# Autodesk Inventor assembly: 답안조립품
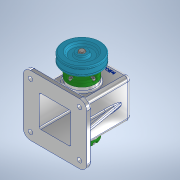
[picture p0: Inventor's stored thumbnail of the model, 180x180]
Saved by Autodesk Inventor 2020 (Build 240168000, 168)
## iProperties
Created: 2022-11
Part Number: 답안조립품
Document SubType Name: Assembly
Designer: USER
Author: USER
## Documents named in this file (16)
- C:\Users\USER\Desktop\721106V1004\답안조립품.iam
- C:\Users\USER\Desktop\721106V1004\본체1.ipt
- C:\Users\USER\Desktop\721106V1004\핀 5 x 18.ipt
- C:\Users\USER\Desktop\721106V1004\V벨트풀리.ipt
- C:\Users\USER\Desktop\721106V1004\고정핀 1.2 x 10.ipt
- C:\Users\USER\Desktop\721106V1004\뒤커버.ipt
- C:\Users\USER\Desktop\721106V1004\링크.ipt
- C:\Users\USER\Desktop\721106V1004\멈춤나사 M3 x 8.ipt
- C:\Users\USER\Desktop\721106V1004\베어링 6201.ipt
- C:\Users\USER\Desktop\721106V1004\볼트 M4 x 12.ipt
- C:\Users\USER\Desktop\721106V1004\부시.ipt
- C:\Users\USER\Desktop\721106V1004\슬라이드.ipt
- C:\Users\USER\Desktop\721106V1004\앞커버.ipt
- C:\Users\USER\Desktop\721106V1004\오일실 12 25 7.ipt
- C:\Users\USER\Desktop\721106V1004\키 4 x 4 x 15.ipt
- C:\Users\USER\Desktop\721106V1004\편심축.ipt
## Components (11 placed, 4 different names)
1. 핀 5 x 18:1
2. V벨트풀리:1
3. 고정핀 1.2 x 10:1
4. ISO 4762 M4 x 12:2
5. ISO 4762 M4 x 12:1
6. ISO 4762 M4 x 12:3
7. ISO 4762 M4 x 12:4
8. ISO 4762 M4 x 12:5
9. ISO 4762 M4 x 12:6
10. ISO 4762 M4 x 12:7
11. ISO 4762 M4 x 12:8
